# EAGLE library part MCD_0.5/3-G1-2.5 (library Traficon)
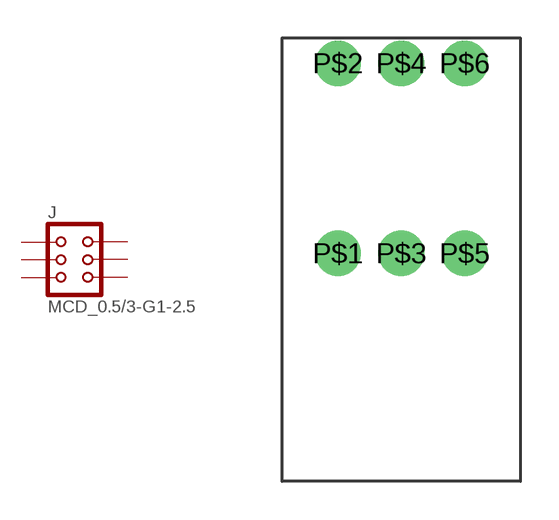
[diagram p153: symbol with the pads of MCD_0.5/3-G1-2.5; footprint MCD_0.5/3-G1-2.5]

Designator prefix J

## MCD_0.5/3-G1-2.5  [MCD_0.5/3-G1-2.5]
P$1  P$1  pas
P$2  P$2  pas
P$3  P$3  pas
P$4  P$4  pas
P$5  P$5  pas
P$6  P$6  pas

## Footprint MCD_0.5/3-G1-2.5 (pad centres in mm)
drill 1.2 round: P$1 -2.88,0.11; P$2 -2.88,7.61; P$3 -0.38,0.11; P$4 -0.38,7.61; P$5 2.12,0.11; P$6 2.12,7.61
